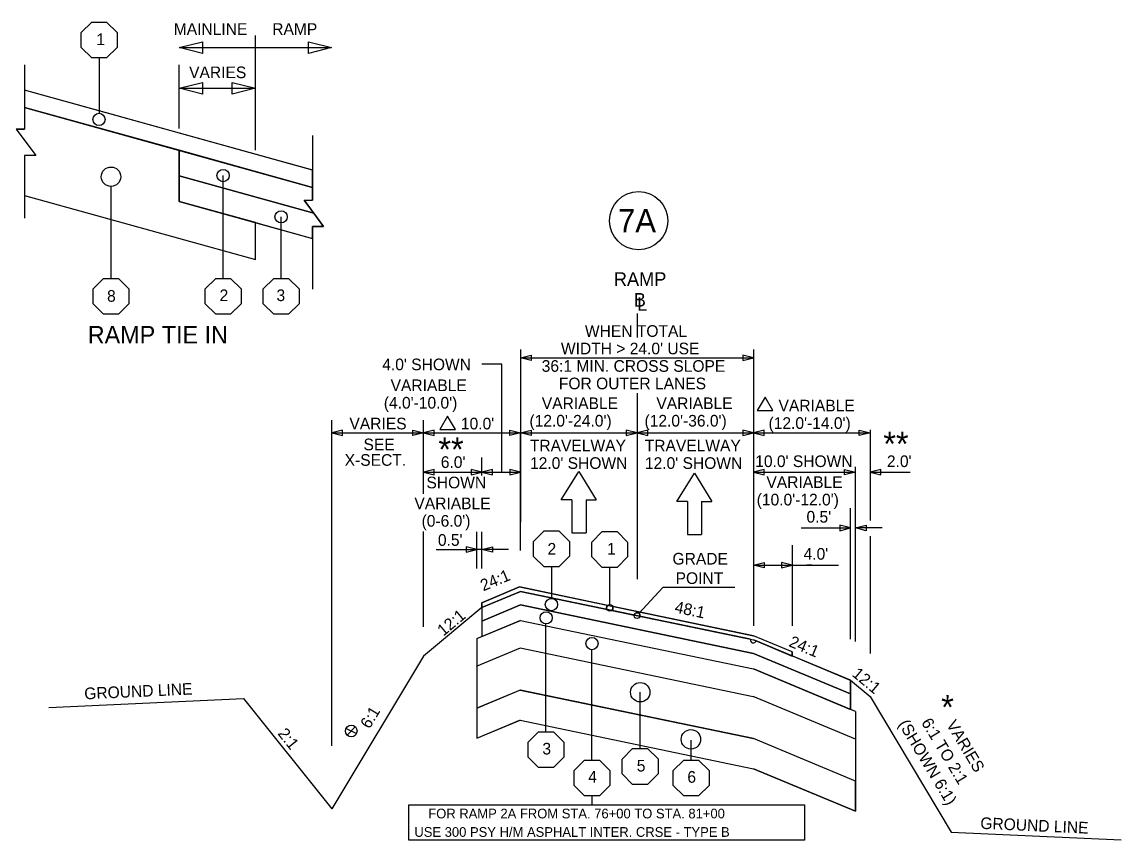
# Model space of a CAD drawing. Extents: x 4649 to 5578, y 4853 to 5383.
# Drawn here: x 5230.6 to 5343.7, y 5063.9 to 5148.2 of the extents above; entities that cross this region are included whole.
import ezdxf

# ---------------------------------------------------------------- set-up
doc = ezdxf.new("R2010")
doc.units = 0
for name, color, linetype in [('Level 25', 7, 'Continuous'), ('RD_QTY_OGFC', 7, 'Continuous'), ('RD_SHT_Bndy', 7, 'Continuous'), ('RD_SHT_Typical', 7, 'Continuous'), ('RD_Sketch1', 7, 'Continuous'), ('RD_Sketch2', 7, 'Continuous'), ('RD_TX_TypSect', 7, 'Continuous'), ('RD_XS_Base', 7, 'Continuous'), ('RD_XS_EarthShd', 7, 'Continuous'), ('RD_XS_Pave', 7, 'Continuous'), ('RD_XS_PaveShd', 7, 'Continuous')]:
    doc.layers.add(name, color=color, linetype=linetype)

# ---------------------------------------------------------------- blocks, each defined once
blk = doc.blocks.new('AH')
at = {"layer": 'RD_XS_PaveShd'}
blk.add_lwpolyline([(-6, 1.5), (0, 0), (-6, -1.5)], close=True, dxfattribs=at)

msp = doc.modelspace()

# ---------------------------------------------------------------- linework, layer by layer
at = {"layer": 'Level 25'}
for p, q in [((5296.57, 5089.93), (5294.09, 5087.27)), ((5303.97, 5089.93), (5296.57, 5089.93))]:
    msp.add_line(p, q, dxfattribs=at)
msp.add_circle((5294.06, 5127.71), 3, dxfattribs=at)
at = {"layer": 'RD_QTY_OGFC'}
for p, q in [((5281.79, 5089.99), (5277.9, 5088.37)), ((5290.88, 5088.1), (5281.79, 5089.99)), ((5277.9, 5087.88), (5281.9, 5089.54)), ((5281.9, 5089.54), (5290.8, 5087.69)), ((5277.9, 5088.37), (5277.9, 5087.88))]:
    msp.add_line(p, q, dxfattribs=at)
msp.add_arc((5291.09, 5087.84), 0.332, 129.1992, 207.7584, dxfattribs=at)
at = {"layer": 'RD_SHT_Bndy'}
for p, q in [((5286.1, 5098.96), (5287.92, 5101.88)), ((5287.92, 5101.88), (5289.7, 5098.95)), ((5297.99, 5098.8), (5299.81, 5101.72)), ((5299.81, 5101.72), (5301.6, 5098.79)), ((5287.19, 5098.96), (5286.1, 5098.96)), ((5287.19, 5098.96), (5287.19, 5095.56)), ((5288.65, 5098.95), (5289.7, 5098.95)), ((5288.65, 5098.95), (5288.65, 5095.55)), ((5299.08, 5098.8), (5297.99, 5098.8)), ((5299.08, 5098.8), (5299.08, 5095.4)), ((5300.54, 5098.79), (5301.6, 5098.79)), ((5300.54, 5098.79), (5300.54, 5095.39)), ((5287.19, 5095.56), (5288.65, 5095.55)), ((5299.08, 5095.4), (5300.54, 5095.39))]:
    msp.add_line(p, q, dxfattribs=at)
at = {"layer": 'RD_SHT_Typical'}
for p, q in [((5230.83, 5143.77), (5230.83, 5137.13)), ((5260.51, 5132.91), (5230.83, 5141.15)), ((5230.83, 5139.38), (5260.48, 5131.14)), ((5229.96, 5137.13), (5231.97, 5134.44)), ((5229.96, 5137.13), (5230.83, 5137.13)), ((5260.48, 5136.47), (5260.48, 5129.83)), ((5230.83, 5134.44), (5230.83, 5127.96)), ((5231.97, 5134.44), (5230.83, 5134.44)), ((5246.76, 5132.32), (5260.62, 5128.47)), ((5246.76, 5129.69), (5260.48, 5125.88)), ((5259.61, 5129.83), (5261.62, 5127.13)), ((5259.61, 5129.83), (5260.48, 5129.83)), ((5260.48, 5127.13), (5260.48, 5120.65)), ((5261.62, 5127.13), (5260.48, 5127.13)), ((5277.9, 5088.37), (5281.79, 5089.99)), ((5277.9, 5087.88), (5281.9, 5089.54)), ((5277.9, 5087.88), (5271.9, 5082.88)), ((5277.9, 5087.88), (5277.9, 5088.37)), ((5277.9, 5086.48), (5281.9, 5088.15)), ((5277.9, 5087.88), (5277.9, 5084.89)), ((5291.3, 5087.58), (5293.6, 5087.1)), ((5294.21, 5087.41), (5291.39, 5087.99)), ((5277.4, 5084.68), (5281.92, 5086.56)), ((5294.09, 5087.27), (5294.21, 5087.41)), ((5294.21, 5087.41), (5294.09, 5087.27)), ((5294.19, 5086.98), (5305.6, 5084.61)), ((5305.89, 5084.97), (5294.21, 5087.41)), ((5277.4, 5084.68), (5277.4, 5074.42)), ((5305.6, 5084.61), (5305.89, 5084.54)), ((5309.89, 5083.31), (5305.89, 5084.97)), ((5309.89, 5083.31), (5305.89, 5084.97)), ((5315.89, 5080.38), (5305.89, 5084.54)), ((5277.37, 5081.84), (5281.9, 5083.72)), ((5315.89, 5078.98), (5305.89, 5083.15)), ((5309.89, 5083.31), (5309.89, 5082.88)), ((5309.89, 5082.88), (5309.89, 5083.31)), ((5271.9, 5082.88), (5262.46, 5067.14)), ((5316.39, 5077.18), (5305.89, 5081.55)), ((5315.89, 5080.38), (5317.89, 5078.7)), ((5315.89, 5080.37), (5315.89, 5077.39)), ((5253.38, 5078.5), (5262.46, 5067.14)), ((5277.4, 5077.52), (5281.9, 5079.39)), ((5316.39, 5074.33), (5305.86, 5078.72)), ((5317.89, 5078.7), (5326.26, 5064.74)), ((5277.4, 5074.42), (5281.9, 5076.3)), ((5316.39, 5077.18), (5316.39, 5066.91)), ((5316.39, 5070.01), (5305.89, 5074.38)), ((5316.39, 5066.91), (5305.89, 5071.28))]:
    msp.add_line(p, q, dxfattribs=at)
for points in [[(5281.79, 5089.99), (5305.89, 5084.97)], [(5281.9, 5089.54), (5305.89, 5084.54)], [(5281.9, 5088.15), (5305.89, 5083.15)], [(5281.9, 5086.55), (5305.89, 5081.55)], [(5294.09, 5087.27), (5294.09, 5087.27)], [(5305.89, 5084.54), (5306.17, 5084.43), (5309.89, 5082.88)], [(5281.87, 5083.71), (5305.86, 5078.72)], [(5309.89, 5082.88), (5309.89, 5082.88)], [(5281.87, 5079.38), (5305.89, 5074.38)], [(5281.87, 5076.29), (5305.89, 5071.28)]]:
    msp.add_lwpolyline(points, dxfattribs=at)
for centre, radius, start, end in [((5291.09, 5087.84), 0.332, 308.7054, 27.2647), ((5293.9, 5087.04), 0.3, 50.3383, 168.2319), ((5293.9, 5087.04), 0.3, 348.2319, 50.3383)]:
    msp.add_arc(centre, radius, start, end, dxfattribs=at)
at = {"layer": 'RD_Sketch1'}
for p, q in [((5233.34, 5077.58), (5253.38, 5078.5)), ((5326.26, 5064.74), (5343.74, 5063.94))]:
    msp.add_line(p, q, dxfattribs=at)
at = {"layer": 'RD_Sketch2'}
for points in [[(5240.35, 5147.09), (5240.35, 5145.56), (5239.27, 5144.48), (5237.74, 5144.48), (5236.65, 5145.56), (5236.65, 5147.09), (5237.74, 5148.17), (5239.27, 5148.17)], [(5241.57, 5120.69), (5241.57, 5119.16), (5240.49, 5118.08), (5238.96, 5118.08), (5237.88, 5119.16), (5237.88, 5120.69), (5238.96, 5121.77), (5240.49, 5121.77)], [(5253.12, 5120.69), (5253.12, 5119.16), (5252.04, 5118.08), (5250.51, 5118.08), (5249.42, 5119.16), (5249.42, 5120.69), (5250.51, 5121.77), (5252.04, 5121.77)], [(5259.09, 5120.68), (5259.09, 5119.15), (5258.01, 5118.07), (5256.48, 5118.07), (5255.4, 5119.15), (5255.4, 5120.68), (5256.48, 5121.77), (5258.01, 5121.77)], [(5286.93, 5094.67), (5286.93, 5093.15), (5285.85, 5092.06), (5284.32, 5092.06), (5283.23, 5093.14), (5283.23, 5094.67), (5284.32, 5095.76), (5285.85, 5095.76)], [(5292.93, 5094.62), (5292.93, 5093.09), (5291.84, 5092.01), (5290.31, 5092.01), (5289.23, 5093.09), (5289.23, 5094.62), (5290.31, 5095.7), (5291.84, 5095.7)], [(5286.37, 5074), (5286.37, 5072.47), (5285.29, 5071.39), (5283.76, 5071.39), (5282.68, 5072.47), (5282.68, 5074), (5283.76, 5075.08), (5285.29, 5075.08)], [(5296.06, 5072.28), (5296.06, 5070.75), (5294.97, 5069.66), (5293.44, 5069.66), (5292.36, 5070.75), (5292.36, 5072.27), (5293.44, 5073.36), (5294.97, 5073.36)], [(5291.11, 5071.08), (5291.11, 5069.55), (5290.03, 5068.47), (5288.5, 5068.47), (5287.42, 5069.55), (5287.42, 5071.08), (5288.5, 5072.17), (5290.03, 5072.17)], [(5301.32, 5071.08), (5301.32, 5069.55), (5300.24, 5068.47), (5298.71, 5068.47), (5297.63, 5069.55), (5297.63, 5071.08), (5298.71, 5072.17), (5300.24, 5072.17)]]:
    msp.add_lwpolyline(points, close=True, dxfattribs=at)
at = {"layer": 'RD_TX_TypSect'}
for p, q in [((5254.6, 5134.96), (5254.6, 5146.78)), ((5246.76, 5145.53), (5254.6, 5145.53)), ((5254.6, 5145.53), (5262.45, 5145.53)), ((5238.5, 5144.48), (5238.5, 5138.77)), ((5246.76, 5137.21), (5246.76, 5143.77)), ((5230.83, 5141.15), (5230.83, 5139.38)), ((5246.76, 5141.35), (5254.6, 5141.35)), ((5230.83, 5139.38), (5246.76, 5134.96)), ((5246.76, 5134.96), (5246.76, 5132.32)), ((5246.76, 5134.96), (5260.48, 5131.14)), ((5260.48, 5131.14), (5260.48, 5132.92)), ((5246.76, 5132.32), (5246.76, 5129.69)), ((5251.27, 5121.77), (5251.27, 5132.36)), ((5239.73, 5121.77), (5239.73, 5131.25)), ((5257.24, 5121.77), (5257.24, 5128.11)), ((5293.9, 5118.17), (5293.9, 5115.68)), ((5281.9, 5114.44), (5281.9, 5096.68)), ((5281.9, 5113.6), (5305.89, 5113.6)), ((5305.89, 5114.44), (5305.89, 5085.98)), ((5279.97, 5112.93), (5277.91, 5112.93)), ((5279.97, 5101.81), (5279.97, 5112.93)), ((5293.9, 5109.95), (5293.9, 5090.8)), ((5262.46, 5073.63), (5262.46, 5107.18)), ((5271.9, 5099.6), (5271.9, 5107.18)), ((5262.46, 5105.85), (5271.9, 5105.85)), ((5271.9, 5105.85), (5281.9, 5105.85)), ((5281.9, 5093.76), (5281.9, 5105.98)), ((5281.9, 5105.85), (5293.9, 5105.85)), ((5293.9, 5105.85), (5305.89, 5105.85)), ((5305.89, 5105.85), (5317.89, 5105.85)), ((5317.89, 5106.19), (5317.89, 5096.82)), ((5277.9, 5101.47), (5277.9, 5103.33)), ((5316.39, 5084.39), (5316.39, 5102.35)), ((5271.9, 5101.81), (5277.9, 5101.81)), ((5277.9, 5101.81), (5281.9, 5101.81)), ((5305.89, 5101.81), (5316.39, 5101.81)), ((5317.89, 5101.81), (5322.03, 5101.81)), ((5315.89, 5084.6), (5315.89, 5098.11)), ((5271.9, 5085.89), (5271.9, 5095.69)), ((5277.4, 5091.89), (5277.4, 5095.67)), ((5277.9, 5091.89), (5277.9, 5095.67)), ((5310.8, 5096.07), (5315.89, 5096.07)), ((5319.15, 5096.07), (5316.39, 5096.07)), ((5317.89, 5095.22), (5317.89, 5083.14)), ((5273.22, 5093.84), (5277.4, 5093.84)), ((5280.67, 5093.84), (5277.4, 5093.84)), ((5309.89, 5094.29), (5309.89, 5085.98)), ((5285.08, 5092.06), (5285.08, 5088.82)), ((5305.89, 5092.24), (5314.65, 5092.24)), ((5311.89, 5092.24), (5311.39, 5092.24)), ((5291.08, 5088.17), (5291.08, 5092.01)), ((5284.51, 5075.08), (5284.51, 5086.18)), ((5289.25, 5072.17), (5289.25, 5083.53)), ((5305.89, 5074.38), (5281.88, 5079.38)), ((5294.22, 5073.36), (5294.22, 5079.17)), ((5277.4, 5077.52), (5277.4, 5074.42)), ((5277.4, 5074.42), (5281.87, 5076.29)), ((5281.87, 5076.29), (5305.89, 5071.28)), ((5263.93, 5075.43), (5265, 5074.89)), ((5264.05, 5074.74), (5264.88, 5075.58)), ((5299.46, 5072.17), (5299.46, 5074.2)), ((5316.39, 5070.01), (5305.89, 5074.38)), ((5305.89, 5071.28), (5316.39, 5066.91)), ((5316.39, 5066.91), (5316.39, 5070.01)), ((5289.26, 5068.47), (5289.26, 5067.55))]:
    msp.add_line(p, q, dxfattribs=at)
for points in [[(5260.48, 5132.92), (5238.5, 5139.02), (5230.83, 5141.15)], [(5281.88, 5079.38), (5281.87, 5079.38), (5277.4, 5077.52)]]:
    msp.add_lwpolyline(points, dxfattribs=at)
for points in [[(5283, 5113.88), (5283, 5113.33), (5281.9, 5113.6)], [(5304.79, 5113.88), (5304.79, 5113.33), (5305.89, 5113.6)], [(5307.08, 5109.55), (5306.28, 5108.16), (5307.88, 5108.16)], [(5274.39, 5107.59), (5273.59, 5106.2), (5275.19, 5106.2)], [(5263.56, 5105.58), (5263.56, 5106.13), (5262.46, 5105.85)], [(5270.8, 5105.58), (5270.8, 5106.13), (5271.9, 5105.85)], [(5273.01, 5105.58), (5273.01, 5106.13), (5271.9, 5105.85)], [(5280.8, 5105.58), (5280.8, 5106.13), (5281.9, 5105.85)], [(5283, 5106.13), (5283, 5105.58), (5281.9, 5105.85)], [(5292.79, 5106.13), (5292.79, 5105.58), (5293.9, 5105.85)], [(5295, 5105.58), (5295, 5106.13), (5293.9, 5105.85)], [(5304.79, 5106.13), (5304.79, 5105.58), (5305.89, 5105.85)], [(5306.99, 5105.58), (5306.99, 5106.13), (5305.89, 5105.85)], [(5316.78, 5105.58), (5316.78, 5106.13), (5317.89, 5105.85)], [(5273.01, 5101.54), (5273.01, 5102.09), (5271.9, 5101.81)], [(5276.8, 5102.09), (5276.8, 5101.54), (5277.9, 5101.81)], [(5279.01, 5101.54), (5279.01, 5102.09), (5277.9, 5101.81)], [(5280.8, 5102.09), (5280.8, 5101.54), (5281.9, 5101.81)], [(5306.99, 5101.54), (5306.99, 5102.09), (5305.89, 5101.81)], [(5315.28, 5101.54), (5315.28, 5102.09), (5316.39, 5101.81)], [(5318.99, 5101.54), (5318.99, 5102.09), (5317.89, 5101.81)], [(5314.78, 5096.34), (5314.78, 5095.79), (5315.89, 5096.07)], [(5317.49, 5096.34), (5317.49, 5095.79), (5316.39, 5096.07)], [(5276.3, 5094.12), (5276.3, 5093.57), (5277.4, 5093.84)], [(5279.01, 5094.12), (5279.01, 5093.57), (5277.9, 5093.84)], [(5306.99, 5092.52), (5306.99, 5091.97), (5305.89, 5092.24)], [(5308.79, 5092.52), (5308.79, 5091.97), (5309.89, 5092.24)], [(5270.4, 5067.55), (5311.13, 5067.55), (5311.13, 5063.93), (5270.4, 5063.93)]]:
    msp.add_lwpolyline(points, close=True, dxfattribs=at)
for centre, radius in [((5238.49, 5138.14), 0.63), ((5238.49, 5138.14), 0.63), ((5239.73, 5132.24), 1), ((5251.27, 5132.36), 0.63), ((5257.24, 5128.11), 0.63), ((5285.08, 5088.18), 0.63), ((5291.09, 5087.84), 0.332), ((5284.54, 5086.81), 0.63), ((5293.9, 5087.04), 0.3), ((5289.26, 5084.16), 0.63), ((5294.23, 5079.15), 1), ((5264.47, 5075.16), 0.6), ((5299.45, 5074.3), 1), ((5299.45, 5074.3), 1)]:
    msp.add_circle(centre, radius, dxfattribs=at)
at = {"layer": 'RD_XS_Base'}
for p, q in [((5260.48, 5131.14), (5246.76, 5134.96)), ((5246.76, 5134.96), (5246.76, 5132.32)), ((5246.76, 5132.32), (5260.62, 5128.47)), ((5260.48, 5129.83), (5260.48, 5131.14)), ((5259.61, 5129.83), (5260.48, 5129.83)), ((5260.62, 5128.47), (5259.61, 5129.83)), ((5281.9, 5089.54), (5277.9, 5087.88)), ((5305.6, 5084.61), (5281.9, 5089.54)), ((5277.9, 5086.48), (5281.9, 5088.15)), ((5277.9, 5087.88), (5277.9, 5086.48)), ((5281.9, 5088.15), (5305.89, 5083.15)), ((5315.89, 5080.37), (5306.17, 5084.43)), ((5305.89, 5083.15), (5315.89, 5078.98)), ((5315.89, 5078.98), (5315.89, 5080.37))]:
    msp.add_line(p, q, dxfattribs=at)
for centre in [(5251.27, 5132.36), (5285.08, 5088.18)]:
    msp.add_circle(centre, 0.63, dxfattribs=at)
msp.add_arc((5305.89, 5084.54), 0.3, 168.2319, 337.3117, dxfattribs=at)
at = {"layer": 'RD_XS_EarthShd'}
for p, q in [((5260.62, 5128.47), (5246.76, 5132.32)), ((5246.76, 5132.32), (5246.76, 5129.69)), ((5246.76, 5129.69), (5254.6, 5127.51)), ((5261.62, 5127.13), (5260.62, 5128.47)), ((5254.6, 5127.51), (5260.48, 5125.88)), ((5260.48, 5125.88), (5260.48, 5127.13)), ((5260.48, 5127.13), (5261.62, 5127.13)), ((5281.9, 5088.15), (5277.9, 5086.48)), ((5305.89, 5083.15), (5281.9, 5088.15)), ((5277.9, 5084.89), (5281.9, 5086.55)), ((5277.9, 5086.48), (5277.9, 5084.89)), ((5281.9, 5086.55), (5305.89, 5081.55)), ((5315.89, 5078.98), (5305.89, 5083.15)), ((5305.89, 5081.55), (5315.89, 5077.39)), ((5315.89, 5077.39), (5315.89, 5078.98))]:
    msp.add_line(p, q, dxfattribs=at)
msp.add_circle((5257.24, 5128.11), 0.63, dxfattribs=at)
at = {"layer": 'RD_XS_Pave'}
for p, q in [((5230.83, 5139.38), (5246.76, 5134.96)), ((5246.76, 5134.96), (5230.83, 5139.38)), ((5230.83, 5139.38), (5230.83, 5137.13)), ((5230.83, 5137.13), (5229.96, 5137.13)), ((5229.96, 5137.13), (5231.97, 5134.44)), ((5231.97, 5134.44), (5230.83, 5134.44)), ((5230.83, 5134.44), (5230.83, 5130.3)), ((5246.76, 5134.96), (5246.76, 5129.69)), ((5230.83, 5130.3), (5254.6, 5123.7)), ((5230.83, 5130.3), (5254.6, 5123.7)), ((5254.6, 5127.51), (5246.76, 5129.69)), ((5254.6, 5123.7), (5254.6, 5127.51)), ((5254.6, 5123.7), (5254.6, 5127.51))]:
    msp.add_line(p, q, dxfattribs=at)
msp.add_lwpolyline([(5246.76, 5129.69), (5246.76, 5132.32), (5246.76, 5134.96)], dxfattribs=at)
msp.add_circle((5239.73, 5132.24), 1, dxfattribs=at)

# ---------------------------------------------------------------- block references
at = {"layer": 'RD_XS_Base', "xscale": 0.4004000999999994, "yscale": 0.4004000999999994, "rotation": 180}
for p in [(5246.76, 5145.53), (5246.76, 5141.35)]:
    msp.add_blockref('AH', p, dxfattribs=at)
at = {"layer": 'RD_XS_PaveShd', "xscale": 0.4000435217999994, "yscale": 0.40004352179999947, "rotation": -0.0014178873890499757}
for p in [(5262.45, 5145.53), (5254.6, 5141.35)]:
    msp.add_blockref('AH', p, dxfattribs=at)

# ---------------------------------------------------------------- texts
at = {"layer": 'Level 25'}
for s, height, p in [('7A', 2.4, (5291.93, 5126.51)), ('RAMP', 1.4, (5291.51, 5121)), ('B ', 1.4, (5293.56, 5118.86)), ('GRADE', 1.2, (5297.55, 5092.3)), ('POINT', 1.2, (5297.87, 5090.3))]:
    msp.add_text(s, height=height, dxfattribs=at).set_placement(p)
at = {"layer": 'RD_TX_TypSect'}
for s, height, p in [('MAINLINE', 1.2, (5246.19, 5146.85)), ('RAMP', 1.2, (5256.33, 5146.85)), ('1', 1.2, (5238.21, 5145.79)), ('VARIES', 1.2, (5247.77, 5142.39)), ('8', 1.2, (5239.32, 5119.36)), ('2', 1.2, (5250.91, 5119.43)), ('3', 1.2, (5256.77, 5119.43)), ('L', 1.4, (5293.92, 5118.43)), ('RAMP TIE IN', 1.8, (5237.33, 5115.07)), ("4.0' SHOWN", 1.2, (5267.66, 5112.31)), ('VARIES', 1.2, (5264.28, 5106.22)), ("10.0'", 1.2, (5275.76, 5106.22)), ('**', 2.5, (5319.26, 5103.48)), ('SEE', 1.2, (5265.73, 5104.07)), ('**', 2.5, (5273.44, 5102.91)), ('X-SECT.', 1.2, (5263.79, 5102.47)), ("6.0'", 1.2, (5273.69, 5102.25)), ("10.0' SHOWN", 1.2, (5306.07, 5102.34)), ("2.0'", 1.2, (5319.63, 5102.34)), ('SHOWN', 1.2, (5272.21, 5100.15)), ("0.5'", 1.2, (5311.35, 5096.62)), ("0.5'", 1.2, (5273.39, 5094.23)), ('2', 1.2, (5284.68, 5093.32)), ('1', 1.2, (5290.82, 5093.33)), ("4.0'", 1.2, (5311.05, 5092.8)), ('*', 2.5, (5325.22, 5076.37)), ('3', 1.2, (5284.15, 5072.74)), ('5', 1.2, (5293.87, 5070.99)), ('4', 1.2, (5288.87, 5069.85)), ('6', 1.2, (5299.08, 5069.83)), ('FOR RAMP 2A FROM STA. 76+00 TO STA. 81+00', 1, (5272.4, 5066.16)), ('USE 300 PSY H/M ASPHALT INTER. CRSE - TYPE B', 1, (5270.97, 5064.26))]:
    msp.add_text(s, height=height, dxfattribs=at).set_placement(p)
for s, rotation, p in [('WHEN TOTAL', 0.0016, (5288.53, 5115.75)), ("WIDTH > 24.0' USE", 0.0016, (5286.06, 5113.95)), ('36:1 MIN. CROSS SLOPE', 0.0016, (5284.08, 5112.15)), ('VARIABLE', 0.0016, (5268.52, 5110.16)), ('FOR OUTER LANES', 0.0016, (5285.85, 5110.35)), ("(4.0'-10.0')", 0.0016, (5267.82, 5108.36)), ('VARIABLE', 0.0016, (5284.09, 5108.31)), ('VARIABLE', 0.0016, (5295.89, 5108.31)), ('VARIABLE', 0.0016, (5308.47, 5108.07)), ("(12.0'-24.0')", 0.0016, (5282.82, 5106.51)), ("(12.0'-36.0')", 0.0016, (5294.67, 5106.51)), ("(12.0'-14.0')", 0.0016, (5307.44, 5106.27)), ('TRAVELWAY', 0.0016, (5282.86, 5103.95)), ('TRAVELWAY', 0.0016, (5294.69, 5103.95)), ("12.0' SHOWN", 0.0016, (5282.88, 5102.15)), ("12.0' SHOWN", 0.0016, (5294.71, 5102.15)), ('VARIABLE', 0.0016, (5307.22, 5100.19)), ('VARIABLE', 0.0016, (5270.97, 5098)), ("(10.0'-12.0')", 0.0016, (5306.22, 5098.39)), ("(0-6.0')", 0.0016, (5271.71, 5096.2)), ('24:1', 22.619, (5278.07, 5089.54)), ('12:1', 39.8056, (5273.95, 5084.87)), ('48:1', 348.2317, (5297.71, 5087.38)), ('24:1', 337.3801, (5309.45, 5083.91)), ('12:1', 320.1939, (5315.96, 5080.89)), ('GROUND LINE', 2.6095, (5237, 5078.41)), ('6:1', 59.0362, (5266.35, 5075.31)), ('(SHOWN 6:1)', 300.9638, (5320.77, 5075.89)), ('6:1 TO 2:1', 300.9638, (5323.13, 5076.04)), ('VARIES', 300.9638, (5325.7, 5075.83)), ('2:1', 308.6598, (5256.84, 5074.87)), ('GROUND LINE', 357.3905, (5329.23, 5065.09))]:
    msp.add_text(s, height=1.2, rotation=rotation, dxfattribs=at).set_placement(p)

doc.saveas('drawing.dxf')
